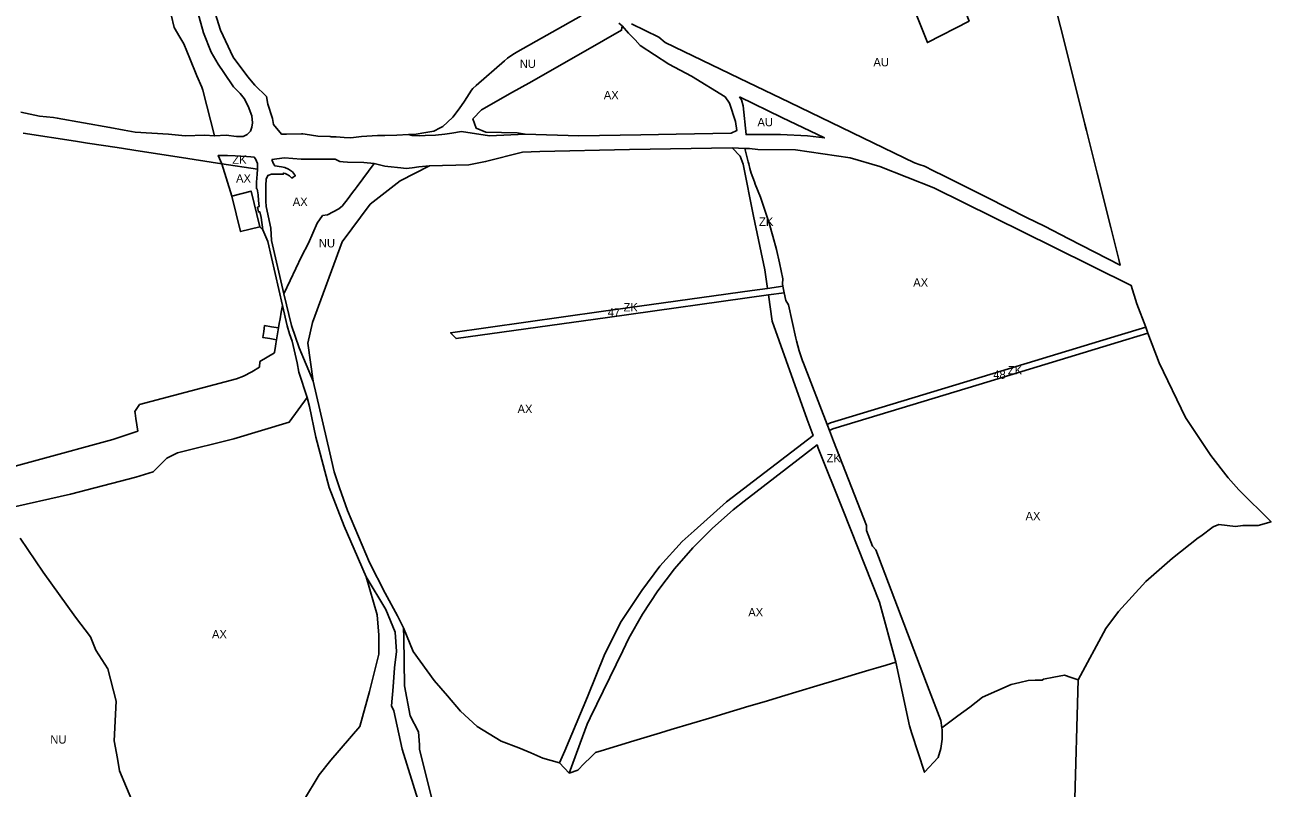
# Model space of a CAD drawing. Extents: x -521939 to -516426, y -1197857 to -1189551.
# Drawn here: x -519377 to -517887, y -1193772 to -1192859 of the extents above; entities that cross this region are included whole.
import ezdxf

# ---------------------------------------------------------------- set-up
doc = ezdxf.new("R2010")
doc.units = 0
for name, color, linetype in [('90710013', 7, 'Continuous'), ('90710023', 7, 'Continuous'), ('90730013', 7, 'Continuous'), ('90750013', 7, 'Continuous'), ('90760013', 7, 'Continuous'), ('ID_navrh', 7, 'Continuous')]:
    doc.layers.add(name, color=color, linetype=linetype)

msp = doc.modelspace()

# ---------------------------------------------------------------- linework, layer by layer
at = {"layer": '90710013'}
for points in [[(-518314.73, -1192837.73), (-518298.12, -1192879.82), (-518248.32, -1192854.07), (-518268.24, -1192802.56), (-518314.73, -1192837.73)], [(-519150.69, -1192991.58), (-519136.83, -1192990.7), (-519124.43, -1192992.31), (-519116.45, -1192992.35), (-519111.6, -1192989.77), (-519107.69, -1192985.77), (-519105.89, -1192981.11), (-519105.28, -1192976), (-519106.04, -1192967.67), (-519110.36, -1192955.97), (-519115.42, -1192946.77), (-519120.04, -1192940.87), (-519128.05, -1192932.59), (-519139.52, -1192915.5), (-519146.39, -1192905.76), (-519154.59, -1192891.1), (-519164.09, -1192868.23), (-519173.07, -1192834.93)], [(-519202.59, -1192846.65), (-519198.9, -1192861.88), (-519192.19, -1192873.4), (-519187.56, -1192881.34), (-519180.36, -1192898.74), (-519171.73, -1192919.56), (-519166.03, -1192933.3), (-519164.66, -1192936.59), (-519150.69, -1192991.58)], [(-518489.33, -1193173.91), (-518471.02, -1193171.35), (-518471.6, -1193168.66), (-518470.85, -1193162.71), (-518475.05, -1193143.47), (-518478.75, -1193127.52), (-518482.9, -1193111.67), (-518487.47, -1193095.95), (-518492.48, -1193080.35), (-518497.9, -1193064.9), (-518503.94, -1193049.14), (-518504.98, -1193046.52), (-518506.92, -1193041.24), (-518508.71, -1193035.9), (-518510.35, -1193030.52), (-518511.83, -1193025.09), (-518512.5, -1193022.36), (-518516.38, -1193006.51), (-518531.81, -1193005.92), (-518522.01, -1193015.8), (-518518.32, -1193025.36), (-518505.93, -1193087.66), (-518492.56, -1193151.65), (-518489.33, -1193173.91)], [(-519099.27, -1193031.44), (-519099.43, -1193024.53), (-519101.64, -1193018.75), (-519103.14, -1193016.99), (-519107.3, -1193016.61), (-519112.45, -1193016.14), (-519126.21, -1193015.42), (-519135.18, -1193014.94), (-519146.2, -1193014.77), (-519142.04, -1193024.85), (-519099.27, -1193031.44)], [(-518280.81, -1193699.82), (-518282.15, -1193690.94), (-518295.93, -1193654.71), (-518359.76, -1193486.89), (-518363.68, -1193482.34), (-518370.97, -1193463.53), (-518371.15, -1193457.53), (-518410.27, -1193356.7), (-518415.16, -1193344.07), (-518417.99, -1193336.8), (-518446.36, -1193263.63), (-518447.5, -1193260.7), (-518449.59, -1193254.77), (-518451.5, -1193248.77), (-518453.21, -1193242.73), (-518454.74, -1193236.63), (-518455.41, -1193233.56), (-518464.15, -1193193.47), (-518467.31, -1193188.37), (-518469.31, -1193179.19), (-518488.19, -1193181.83), (-518483.68, -1193213.33), (-518442.04, -1193330.76), (-518434.69, -1193349.86), (-518485.73, -1193389.02), (-518538.28, -1193429.5), (-518577.2, -1193463.96), (-518591.51, -1193476.86), (-518618.18, -1193506.33), (-518639.59, -1193535.59), (-518664.37, -1193572.73), (-518683.73, -1193611.33), (-518704.53, -1193662.76), (-518731.88, -1193727.36), (-518738.18, -1193741.84), (-518726.44, -1193753.95), (-518710.8, -1193710.67), (-518704.88, -1193695.38), (-518701.31, -1193688), (-518662.41, -1193607.53), (-518655.18, -1193592.58), (-518638.78, -1193563.71), (-518620.51, -1193535.98), (-518600.44, -1193509.51), (-518578.67, -1193484.44), (-518555.29, -1193460.85), (-518530.41, -1193438.86), (-518517.26, -1193428.71), (-518430.16, -1193361.31), (-518428.58, -1193365.29), (-518398.79, -1193439.68), (-518355.54, -1193549.59), (-518335.93, -1193621.27), (-518319.66, -1193697.29), (-518316.66, -1193706.74), (-518301.75, -1193752.95), (-518285.29, -1193735.47), (-518282.05, -1193724.63), (-518280.43, -1193713.43), (-518280.46, -1193702.12), (-518280.81, -1193699.82)]]:
    msp.add_lwpolyline(points, dxfattribs=at)
at = {"layer": '90710023'}
for points in [[(-518489.33, -1193173.91), (-518507.69, -1193176.48), (-518688.29, -1193201.76), (-518868.39, -1193226.97), (-518861.71, -1193234.11), (-518680.88, -1193208.8), (-518488.19, -1193181.83), (-518469.31, -1193179.19), (-518471.02, -1193171.35), (-518489.33, -1193173.91)], [(-518037.03, -1193220.36), (-518069.91, -1193230.34), (-518241.69, -1193282.48), (-518414.03, -1193334.79), (-518417.99, -1193336.8), (-518415.16, -1193344.07), (-518411.17, -1193342.06), (-518236.07, -1193288.88), (-518060.97, -1193235.7), (-518034.3, -1193227.6), (-518037.03, -1193220.36)]]:
    msp.add_lwpolyline(points, dxfattribs=at)
at = {"layer": '90730013'}
for points in [[(-518712.04, -1192847.75), (-518787.8, -1192890.35), (-518792.08, -1192892.91), (-518796.23, -1192895.68), (-518800.23, -1192898.65), (-518804.08, -1192901.83), (-518837.69, -1192931.06), (-518841.93, -1192934.75), (-518843.32, -1192936.91), (-518851.6, -1192949.85), (-518858.28, -1192959.18), (-518865.75, -1192969.09), (-518872.22, -1192975.24), (-518877.56, -1192980.06), (-518880.78, -1192981.82), (-518888.53, -1192985.94), (-518897.98, -1192987.5), (-518912.11, -1192989.78), (-518918.87, -1192990)], [(-518918.87, -1192990), (-518914.36, -1192990.89), (-518911.52, -1192991.08), (-518905.82, -1192991.22), (-518898.64, -1192990.98), (-518886.48, -1192990.45), (-518875.1, -1192989.54), (-518866.91, -1192988.22), (-518855.17, -1192986.26), (-518821.67, -1192991.23), (-518779.05, -1192989.61), (-518788.86, -1192987.81), (-518826.37, -1192986.96), (-518837.66, -1192982.24), (-518841.74, -1192971.22), (-518831.52, -1192960.42), (-518794.45, -1192939.2), (-518774.96, -1192928.3), (-518707.15, -1192889.79), (-518663.78, -1192865.16), (-518663.19, -1192859.9), (-518667.06, -1192856.49)], [(-519032.72, -1193285.1), (-519039.05, -1193239.66), (-519033.58, -1193214.67), (-518998.24, -1193118.29), (-518964.46, -1193073.28), (-518928.64, -1193045.14), (-518893.72, -1193027.32), (-518906.5, -1193028.54), (-518914.19, -1193029.54), (-518921.63, -1193030.5), (-518927.91, -1193029.78), (-518943.36, -1193028), (-518946.89, -1193027.59), (-518956.41, -1193025.34), (-518959.64, -1193024.58), (-518980, -1193052), (-518982.48, -1193055.34), (-518985.57, -1193059.25), (-518992.15, -1193068.17), (-518997.03, -1193074.16), (-518997.79, -1193075.34), (-519002.06, -1193078.67), (-519015.43, -1193086.04), (-519021.48, -1193086.74), (-519027.86, -1193095.83), (-519038.42, -1193119.66), (-519046.53, -1193135.65), (-519060.07, -1193164.39), (-519067.63, -1193180.4), (-519058.78, -1193218.39), (-519049.46, -1193245.15), (-519032.72, -1193285.1)], [(-519400.65, -1193437.87), (-519323.14, -1193420.3), (-519244.63, -1193400.06), (-519224.13, -1193393.57), (-519216.77, -1193386.17), (-519207.67, -1193377.01), (-519195.16, -1193370.61), (-519127.73, -1193353.98), (-519061.29, -1193334.23), (-519040.03, -1193304.65), (-519049.8, -1193274.26), (-519051.78, -1193263.19), (-519057.96, -1193237.27), (-519061.2, -1193228.34), (-519063.8, -1193218.73), (-519069.34, -1193194.44), (-519070.87, -1193202.49), (-519072.39, -1193210.54), (-519073.35, -1193215.87), (-519074.18, -1193221.13), (-519075.3, -1193228.25), (-519076.43, -1193235.38), (-519077.23, -1193240.44), (-519077.66, -1193243.14), (-519078.88, -1193250.88), (-519078.88, -1193250.89), (-519078.89, -1193250.9), (-519087.73, -1193256.2), (-519096.57, -1193261.51), (-519097.04, -1193268.18), (-519106.02, -1193274.02), (-519115.87, -1193279.15), (-519124.36, -1193282.37), (-519240.31, -1193313.01), (-519245.94, -1193321.3), (-519245.64, -1193323.44), (-519244.89, -1193329.7), (-519242.56, -1193344.82), (-519272.27, -1193354.6), (-519363, -1193379.33), (-519414.21, -1193393.4)], [(-519244.01, -1193799.73), (-519255.98, -1193771.28), (-519264.33, -1193751.44), (-519266.62, -1193736.71), (-519270.68, -1193715.28), (-519268.16, -1193667.94), (-519278.45, -1193629.39), (-519292.71, -1193607.08), (-519298.97, -1193590.8), (-519316.99, -1193567.29), (-519355.68, -1193513.49), (-519383.3, -1193472.91)], [(-518907.68, -1193785.6), (-518926.27, -1193725.26), (-518936.17, -1193679.58), (-518938.89, -1193673.47), (-518936.87, -1193650.95), (-518935.29, -1193627.86), (-518933.01, -1193608.51), (-518934.47, -1193585.52), (-518945.93, -1193558.15), (-518969.16, -1193519.14), (-518956.05, -1193564.77), (-518954.36, -1193589.13), (-518954.36, -1193611.78), (-518965.26, -1193656.42), (-518977.05, -1193698.16), (-519011.53, -1193738.42), (-519025.65, -1193756.19), (-519062.93, -1193818.34)], [(-518280.81, -1193699.82), (-518280.46, -1193702.12), (-518280.43, -1193713.43), (-518282.05, -1193724.63), (-518285.29, -1193735.47), (-518301.75, -1193752.95), (-518316.66, -1193706.74), (-518319.66, -1193697.29), (-518335.93, -1193621.27), (-518347.46, -1193624.73), (-518359.78, -1193628.44), (-518368.17, -1193630.96), (-518383.95, -1193635.7), (-518407.66, -1193642.82), (-518430.5, -1193649.69), (-518472.55, -1193662.32), (-518489.27, -1193667.35), (-518515.5, -1193675.23), (-518522.07, -1193677.2), (-518534.15, -1193680.83), (-518555.76, -1193687.33), (-518604.52, -1193701.98), (-518617.19, -1193705.79), (-518649.38, -1193715.46), (-518688.32, -1193727.16), (-518695.08, -1193729.19), (-518700.77, -1193734.93), (-518708.43, -1193742.66), (-518716.1, -1193750.4), (-518726.44, -1193753.95), (-518738.18, -1193741.84), (-518758.22, -1193736), (-518772.5, -1193729.81), (-518786.78, -1193723.63), (-518807.88, -1193715.75), (-518822.3, -1193707.06), (-518836.72, -1193698.38), (-518856.41, -1193680), (-518872.2, -1193661.68), (-518888, -1193643.37), (-518913.16, -1193608.62), (-518924.55, -1193580.35), (-518924.44, -1193591.77), (-518923.59, -1193649.53), (-518916.83, -1193685.28), (-518906.72, -1193704.58), (-518905.61, -1193720.26), (-518905.57, -1193725.38), (-518886.46, -1193802.5)], [(-518122.17, -1193798.73), (-518117.92, -1193642.32), (-518126.04, -1193639.54), (-518134.15, -1193636.76), (-518146.78, -1193639.21), (-518159.42, -1193641.67), (-518160.69, -1193642.79), (-518169.12, -1193642.95), (-518177.56, -1193643.12), (-518187.67, -1193645.56), (-518197.78, -1193648), (-518215.03, -1193655.62), (-518232.28, -1193663.25), (-518247.56, -1193675.13), (-518261.76, -1193685.67), (-518275.96, -1193696.22), (-518280.81, -1193699.82)]]:
    msp.add_lwpolyline(points, dxfattribs=at)
at = {"layer": '90750013'}
for points in [[(-518651.89, -1192857.45), (-518619.45, -1192873.36), (-518611.95, -1192879.61), (-518611.93, -1192879.62), (-518523.11, -1192922.54), (-518462.75, -1192951.72), (-518313.58, -1193023.8), (-518313.55, -1193023.81), (-518306.65, -1193026.04), (-518301.5, -1193027.7), (-518290.64, -1193033.2), (-518278.49, -1193039.24), (-518225.89, -1193065.68), (-518179.48, -1193089.1), (-518158.26, -1193099.67), (-518128.95, -1193114.67), (-518067.56, -1193146.04), (-518069.18, -1193139.58), (-518078.88, -1193100.92), (-518095.16, -1193036.02), (-518107.93, -1192985.11), (-518109.82, -1192977.58), (-518135.12, -1192876.72), (-518151.23, -1192812.5)], [(-519156.37, -1192823.91), (-519143.51, -1192865.04), (-519128.56, -1192897.44), (-519110.71, -1192920.84), (-519102.51, -1192930.9), (-519088.52, -1192944.47), (-519086.92, -1192953.51), (-519086.7, -1192954.76), (-519082.2, -1192968.42), (-519081.47, -1192970.65), (-519080.25, -1192977.67), (-519070.65, -1192989.38), (-519064.74, -1192989.25), (-519046.88, -1192988.85), (-519044.97, -1192989.14), (-519042.16, -1192989.58), (-519026.96, -1192991.92), (-519012.24, -1192992.37), (-519011.01, -1192992.42), (-519005.4, -1192992.65), (-518995.54, -1192993.27), (-518987.7, -1192993.82), (-518974.8, -1192992.13), (-518955.94, -1192991.19), (-518947.06, -1192990.9), (-518932.53, -1192990.45), (-518918.87, -1192990)], [(-518248.32, -1192854.07), (-518298.12, -1192879.82), (-518314.73, -1192837.73)], [(-518918.87, -1192990), (-518912.11, -1192989.78), (-518897.98, -1192987.5), (-518888.53, -1192985.94), (-518880.78, -1192981.82), (-518877.56, -1192980.06), (-518872.22, -1192975.24), (-518865.75, -1192969.09), (-518858.28, -1192959.18), (-518851.6, -1192949.85), (-518843.32, -1192936.91), (-518841.93, -1192934.75), (-518837.69, -1192931.06), (-518804.08, -1192901.83), (-518800.23, -1192898.65), (-518796.23, -1192895.68), (-518792.08, -1192892.91), (-518787.8, -1192890.35), (-518712.04, -1192847.75)], [(-518522.92, -1192944.85), (-518520.44, -1192948.52), (-518518.64, -1192955.67), (-518515.05, -1192990), (-518473.62, -1192989.89), (-518441.46, -1192991.31), (-518421.27, -1192993.97), (-518472.09, -1192969.41), (-518522.92, -1192944.85)]]:
    msp.add_lwpolyline(points, dxfattribs=at)
at = {"layer": '90760013'}
for points in [[(-519382.21, -1192963.28), (-519360.04, -1192967.68), (-519343.21, -1192969.49), (-519338.88, -1192970.21), (-519275.79, -1192981.35), (-519258.65, -1192984.65), (-519245.61, -1192987.01), (-519225.72, -1192988.29), (-519205.81, -1192989.39), (-519186.01, -1192991.26), (-519162.1, -1192990.71), (-519150.69, -1192991.58), (-519164.66, -1192936.59), (-519166.03, -1192933.3), (-519171.73, -1192919.56), (-519180.36, -1192898.74), (-519187.56, -1192881.34), (-519192.19, -1192873.4), (-519198.9, -1192861.88), (-519202.59, -1192846.65)], [(-518532.67, -1192988.21), (-518525.88, -1192984.87), (-518527.68, -1192974.39), (-518534.83, -1192952.24), (-518539.85, -1192944.8), (-518580.39, -1192919.85), (-518607.43, -1192905.72), (-518641.65, -1192883.29), (-518647.77, -1192876.73), (-518655.74, -1192868.43), (-518663.19, -1192859.9), (-518663.78, -1192865.16), (-518707.15, -1192889.79), (-518774.96, -1192928.3), (-518794.45, -1192939.2), (-518831.52, -1192960.42), (-518841.74, -1192971.22), (-518837.66, -1192982.24), (-518826.37, -1192986.96), (-518788.86, -1192987.81), (-518779.05, -1192989.61), (-518715.07, -1192991.54), (-518640.83, -1192990.3), (-518598.55, -1192989.35), (-518532.67, -1192988.21)], [(-519076.43, -1193235.38), (-519084.6, -1193234.09), (-519092.77, -1193232.8), (-519091.82, -1193225.66), (-519090.87, -1193218.52), (-519082.52, -1193219.82), (-519074.18, -1193221.13), (-519073.35, -1193215.87), (-519072.39, -1193210.54), (-519070.87, -1193202.49), (-519069.34, -1193194.44), (-519086.83, -1193117.76), (-519092.79, -1193103.81), (-519096.56, -1193100.18), (-519119.61, -1193106.06), (-519130.14, -1193063.54), (-519142.04, -1193024.85), (-519195.48, -1193016.56), (-519239.74, -1193009.74), (-519267.23, -1193005.51), (-519302.57, -1193000.06), (-519316.79, -1192997.86), (-519379.4, -1192988.21)], [(-518489.33, -1193173.91), (-518492.56, -1193151.65), (-518505.93, -1193087.66), (-518518.32, -1193025.36), (-518522.01, -1193015.8), (-518531.81, -1193005.92), (-518654.27, -1193007.7), (-518761.5, -1193009.97), (-518782.28, -1193010.93), (-518826.54, -1193022.13), (-518846.7, -1193025.98), (-518893.72, -1193027.32), (-518928.64, -1193045.14), (-518964.46, -1193073.28), (-518998.24, -1193118.29), (-519033.58, -1193214.67), (-519039.05, -1193239.66), (-519032.72, -1193285.1), (-519012.64, -1193370.77), (-519007.46, -1193393.47), (-519001.34, -1193412.48), (-518991.48, -1193439.69), (-518965.5, -1193501.95), (-518946.48, -1193538.74), (-518931.74, -1193565.63), (-518924.55, -1193580.35), (-518913.16, -1193608.62), (-518888, -1193643.37), (-518872.2, -1193661.68), (-518856.41, -1193680), (-518836.72, -1193698.38), (-518822.3, -1193707.06), (-518807.88, -1193715.75), (-518786.78, -1193723.63), (-518772.5, -1193729.81), (-518758.22, -1193736), (-518738.18, -1193741.84), (-518731.88, -1193727.36), (-518704.53, -1193662.76), (-518683.73, -1193611.33), (-518664.37, -1193572.73), (-518639.59, -1193535.59), (-518618.18, -1193506.33), (-518591.51, -1193476.86), (-518577.2, -1193463.96), (-518538.28, -1193429.5), (-518485.73, -1193389.02), (-518434.69, -1193349.86), (-518442.04, -1193330.76), (-518483.68, -1193213.33), (-518488.19, -1193181.83), (-518680.88, -1193208.8), (-518861.71, -1193234.11), (-518868.39, -1193226.97), (-518688.29, -1193201.76), (-518507.69, -1193176.48), (-518489.33, -1193173.91)], [(-518037.03, -1193220.36), (-518047.58, -1193192.34), (-518054.34, -1193170.39), (-518147.01, -1193124.62), (-518290.52, -1193053.74), (-518355.07, -1193028.15), (-518390.51, -1193017.79), (-518455.87, -1193008.08), (-518500.8, -1193007.81), (-518511.04, -1193006.71), (-518516.38, -1193006.51), (-518512.5, -1193022.36), (-518511.83, -1193025.09), (-518510.35, -1193030.52), (-518508.71, -1193035.9), (-518506.92, -1193041.24), (-518504.98, -1193046.52), (-518503.94, -1193049.14), (-518497.9, -1193064.9), (-518492.48, -1193080.35), (-518487.47, -1193095.95), (-518482.9, -1193111.67), (-518478.75, -1193127.52), (-518475.05, -1193143.47), (-518470.85, -1193162.71), (-518471.6, -1193168.66), (-518471.02, -1193171.35), (-518469.31, -1193179.19), (-518467.31, -1193188.37), (-518464.15, -1193193.47), (-518455.41, -1193233.56), (-518454.74, -1193236.63), (-518453.21, -1193242.73), (-518451.5, -1193248.77), (-518449.59, -1193254.77), (-518447.5, -1193260.7), (-518446.36, -1193263.63), (-518417.99, -1193336.8), (-518414.03, -1193334.79), (-518241.69, -1193282.48), (-518069.91, -1193230.34), (-518037.03, -1193220.36)], [(-519082.01, -1193019.86), (-519080.51, -1193024.08), (-519078.69, -1193027.26), (-519070.56, -1193028.61), (-519066.57, -1193029.49), (-519062.38, -1193031.14), (-519057.59, -1193034.55), (-519054.97, -1193037.51), (-519054.02, -1193039.03), (-519058.32, -1193041.95), (-519060.88, -1193039.35), (-519063.71, -1193037.53), (-519066.12, -1193036.54), (-519068.36, -1193036.01), (-519068.53, -1193037.41), (-519078.8, -1193037.27), (-519082.67, -1193037.22), (-519087.08, -1193038.9), (-519089.11, -1193043.23), (-519089.5, -1193051.02), (-519089.42, -1193069.44), (-519088.85, -1193075.94), (-519083.39, -1193101.82), (-519082.57, -1193116.69), (-519067.63, -1193180.4), (-519060.07, -1193164.39), (-519046.53, -1193135.65), (-519038.42, -1193119.66), (-519027.86, -1193095.83), (-519021.48, -1193086.74), (-519015.43, -1193086.04), (-519002.06, -1193078.67), (-518997.79, -1193075.34), (-518997.03, -1193074.16), (-518992.15, -1193068.17), (-518985.57, -1193059.25), (-518982.48, -1193055.34), (-518980, -1193052), (-518959.64, -1193024.58), (-518972.24, -1193023.25), (-518991.81, -1193022.8), (-518996.85, -1193022.41), (-519000.94, -1193022.11), (-519006.51, -1193019.53), (-519008.43, -1193019.45), (-519016.37, -1193019.41), (-519025.46, -1193019.32), (-519046.96, -1193019.18), (-519067.01, -1193017.55), (-519082.01, -1193019.86)], [(-519096.56, -1193100.18), (-519092.79, -1193103.81), (-519094.99, -1193089.06), (-519096.34, -1193082.48), (-519098.12, -1193082.46), (-519099.18, -1193076.82), (-519097.38, -1193076.11), (-519098.14, -1193068.98), (-519098.49, -1193062.14), (-519099.79, -1193055.02), (-519100.47, -1193055.02), (-519100.42, -1193046.7), (-519099.54, -1193037.16), (-519099.27, -1193031.44), (-519142.04, -1193024.85), (-519130.14, -1193063.54), (-519107.08, -1193057.58), (-519096.56, -1193100.18)], [(-518280.81, -1193699.82), (-518275.96, -1193696.22), (-518261.76, -1193685.67), (-518247.56, -1193675.13), (-518232.28, -1193663.25), (-518215.03, -1193655.62), (-518197.78, -1193648), (-518187.67, -1193645.56), (-518177.56, -1193643.12), (-518169.12, -1193642.95), (-518160.69, -1193642.79), (-518159.42, -1193641.67), (-518146.78, -1193639.21), (-518134.15, -1193636.76), (-518126.04, -1193639.54), (-518117.92, -1193642.32), (-518084.56, -1193581.03), (-518069.66, -1193560.73), (-518036.86, -1193524.72), (-518004.98, -1193496.63), (-517974.13, -1193472.43), (-517971.27, -1193470.3), (-517956.24, -1193459.13), (-517949.48, -1193456.49), (-517929.64, -1193459.01), (-517920.81, -1193457.64), (-517902.58, -1193457.64), (-517887.1, -1193453.28), (-517925.8, -1193415.15), (-517938.3, -1193400.82), (-517959.05, -1193374.1), (-517989.44, -1193328.34), (-518020.98, -1193262.98), (-518034.3, -1193227.6), (-518060.97, -1193235.7), (-518236.07, -1193288.88), (-518411.17, -1193342.06), (-518415.16, -1193344.07), (-518410.27, -1193356.7), (-518371.15, -1193457.53), (-518370.97, -1193463.53), (-518363.68, -1193482.34), (-518359.76, -1193486.89), (-518295.93, -1193654.71), (-518282.15, -1193690.94), (-518280.81, -1193699.82)], [(-519414.21, -1193393.4), (-519363, -1193379.33), (-519272.27, -1193354.6), (-519242.56, -1193344.82), (-519244.89, -1193329.7), (-519245.64, -1193323.44), (-519245.94, -1193321.3), (-519240.31, -1193313.01), (-519124.36, -1193282.37), (-519115.87, -1193279.15), (-519106.02, -1193274.02), (-519097.04, -1193268.18), (-519096.57, -1193261.51), (-519087.73, -1193256.2), (-519078.89, -1193250.9), (-519078.88, -1193250.89), (-519078.88, -1193250.88), (-519077.66, -1193243.14), (-519077.23, -1193240.44), (-519076.43, -1193235.38)], [(-518969.16, -1193519.14), (-518983.73, -1193485.98), (-518995.72, -1193458.59), (-519013.6, -1193412.23), (-519029.64, -1193352.06), (-519037.03, -1193315.32), (-519040.03, -1193304.65), (-519061.29, -1193334.23), (-519127.73, -1193353.98), (-519195.16, -1193370.61), (-519207.67, -1193377.01), (-519216.77, -1193386.17), (-519224.13, -1193393.57), (-519244.63, -1193400.06), (-519323.14, -1193420.3), (-519400.65, -1193437.87)], [(-518335.93, -1193621.27), (-518355.54, -1193549.59), (-518398.79, -1193439.68), (-518428.58, -1193365.29), (-518430.16, -1193361.31), (-518517.26, -1193428.71), (-518530.41, -1193438.86), (-518555.29, -1193460.85), (-518578.67, -1193484.44), (-518600.44, -1193509.51), (-518620.51, -1193535.98), (-518638.78, -1193563.71), (-518655.18, -1193592.58), (-518662.41, -1193607.53), (-518701.31, -1193688), (-518704.88, -1193695.38), (-518710.8, -1193710.67), (-518726.44, -1193753.95), (-518716.1, -1193750.4), (-518708.43, -1193742.66), (-518700.77, -1193734.93), (-518695.08, -1193729.19), (-518688.32, -1193727.16), (-518649.38, -1193715.46), (-518617.19, -1193705.79), (-518604.52, -1193701.98), (-518555.76, -1193687.33), (-518534.15, -1193680.83), (-518522.07, -1193677.2), (-518515.5, -1193675.23), (-518489.27, -1193667.35), (-518472.55, -1193662.32), (-518430.5, -1193649.69), (-518407.66, -1193642.82), (-518383.95, -1193635.7), (-518368.17, -1193630.96), (-518359.78, -1193628.44), (-518347.46, -1193624.73), (-518335.93, -1193621.27)], [(-519383.3, -1193472.91), (-519355.68, -1193513.49), (-519316.99, -1193567.29), (-519298.97, -1193590.8), (-519292.71, -1193607.08), (-519278.45, -1193629.39), (-519268.16, -1193667.94), (-519270.68, -1193715.28), (-519266.62, -1193736.71), (-519264.33, -1193751.44), (-519255.98, -1193771.28), (-519244.01, -1193799.73)], [(-519062.93, -1193818.34), (-519025.65, -1193756.19), (-519011.53, -1193738.42), (-518977.05, -1193698.16), (-518965.26, -1193656.42), (-518954.36, -1193611.78), (-518954.36, -1193589.13), (-518956.05, -1193564.77), (-518969.16, -1193519.14)]]:
    msp.add_lwpolyline(points, dxfattribs=at)

# ---------------------------------------------------------------- texts
at = {"layer": '90710013'}
for rotation, p in [(0, (-519129.41, -1193024.84)), (360, (-518418.73, -1193382.19))]:
    msp.add_text('ZK', height=10, rotation=rotation, dxfattribs=at).set_placement(p)
msp.add_text('ZK', height=10, dxfattribs=at).set_placement((-518499.46, -1193099.12))
at = {"layer": '90710023'}
for rotation, p in [(360, (-518661.6, -1193201.61)), (0, (-518201.99, -1193276.89))]:
    msp.add_text('ZK', height=10, rotation=rotation, dxfattribs=at).set_placement(p)
at = {"layer": '90730013'}
for rotation, p in [(360, (-518785.71, -1192910.08)), (0, (-519025.9, -1193124.93)), (360, (-519347.12, -1193718.7))]:
    msp.add_text('NU', height=10, rotation=rotation, dxfattribs=at).set_placement(p)
at = {"layer": '90750013'}
for rotation, p in [(360, (-518362.71, -1192908.25)), (0, (-518501.4, -1192980))]:
    msp.add_text('AU', height=10, rotation=rotation, dxfattribs=at).set_placement(p)
at = {"layer": '90760013'}
for rotation, p in [(0, (-518685.17, -1192947.68)), (360, (-519124.97, -1193047.34)), (360, (-519057.17, -1193075.32)), (360, (-518315.12, -1193171.87)), (0, (-518788.3, -1193323.27)), (360, (-518180.76, -1193451.42)), (0, (-518512.38, -1193566.55)), (360, (-519153.74, -1193592.76))]:
    msp.add_text('AX', height=10, rotation=rotation, dxfattribs=at).set_placement(p)
at = {"layer": 'ID_navrh'}
for s, rotation, p in [('47', 0, (-518680.46, -1193207.64)), ('48', 360, (-518219.35, -1193282.14))]:
    msp.add_text(s, height=10, rotation=rotation, dxfattribs=at).set_placement(p)

doc.saveas('drawing.dxf')
